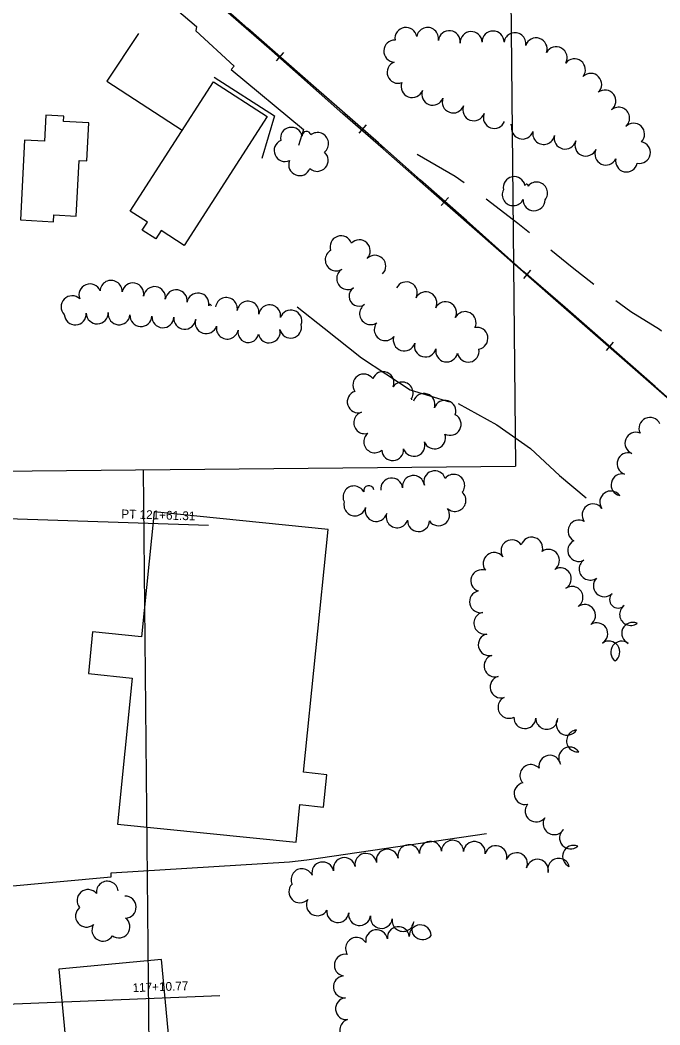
# Model space of a CAD drawing. Extents: x -25029 to 2274964, y -81170 to 687028.
# Drawn here: x -3935 to -3352, y -68032 to -67116 of the extents above; entities that cross this region are included whole.
import ezdxf

# ---------------------------------------------------------------- set-up
doc = ezdxf.new("R2010")
doc.units = 0
for name, color, linetype in [('BLDG', 7, 'Continuous'), ('Default', 7, 'Continuous'), ('DRIVWY', 7, 'Continuous'), ('RD_X_RR_1', 7, 'Continuous'), ('RR', 7, 'Continuous'), ('TREES', 7, 'Continuous'), ('WALL', 7, 'Continuous')]:
    doc.layers.add(name, color=color, linetype=linetype)

msp = doc.modelspace()

# ---------------------------------------------------------------- linework, layer by layer
at = {"layer": 'BLDG'}
for points in [[(-3710.3, -67204.07), (-3786, -67321.41), (-3806.95, -67307.9), (-3811.76, -67315.36), (-3824.04, -67307.44), (-3819.45, -67300.33), (-3835.17, -67290.19), (-3759.24, -67172.5)], [(-3905.01, -67299.85), (-3904.67, -67293.63), (-3884.3, -67294.72), (-3881.59, -67243.98), (-3874.52, -67244.36), (-3872.67, -67209.82), (-3895.96, -67208.57), (-3895.7, -67203.75), (-3911.85, -67202.88), (-3913.11, -67226.38), (-3931.26, -67225.41), (-3935.16, -67298.24)], [(-3683.93, -67865.26), (-3680.45, -67831.07), (-3658.95, -67833.25), (-3655.95, -67803.75), (-3677.34, -67801.58), (-3654.84, -67580.2), (-3813.11, -67564.12), (-3824.71, -67678.2), (-3869.31, -67673.67), (-3873.17, -67711.69), (-3833.21, -67715.75), (-3846.72, -67848.72)], [(-3856.97, -68100.09), (-3854.77, -68123.29), (-3834.57, -68121.38), (-3836.68, -68099.04), (-3794.95, -68095.09), (-3806.6, -67972.04), (-3899.99, -67980.88), (-3888.43, -68103.06)]]:
    msp.add_lwpolyline(points, close=True, dxfattribs=at)
at = {"layer": 'Default'}
for p, q in [((-3498.71, -66025.16), (-3484.02, -67522.6)), ((-4383.92, -67531.43), (-3484.02, -67522.6)), ((-3823.15, -67525.93), (-3813.45, -68514.64)), ((-4053.51, -67566.81), (-3763.85, -67576.44)), ((-4033.08, -68016.42), (-3753.55, -68005.06))]:
    msp.add_line(p, q, dxfattribs=at)
at = {"layer": 'DRIVWY'}
for points in [[(-3573.51, -67238.36), (-3538.86, -67258.18), (-3530.73, -67264.14)], [(-3510.65, -67279.04), (-3481.94, -67301.14), (-3471.22, -67309.78)], [(-3451.76, -67325.47), (-3432.45, -67341.11), (-3412.77, -67356.77)], [(-3392.72, -67371.68), (-3378.81, -67381.6), (-3352.85, -67397.87), (-3351.09, -67399.32)]]:
    msp.add_lwpolyline(points, dxfattribs=at)
at = {"layer": 'RD_X_RR_1'}
msp.add_lwpolyline([(-3338.49, -67466.69), (-3394.3, -67417.71), (-3449.6, -67369.51), (-3501.5, -67323.97), (-3560.76, -67272.02), (-3604.74, -67233.4), (-3641.21, -67201.63), (-3705.92, -67144.26), (-3766.77, -67090.93)], dxfattribs=at)
at = {"layer": 'RR'}
for p, q in [((-3695.37, -67145.65), (-3701.99, -67153.14)), ((-3620.24, -67211.6), (-3626.82, -67219.13)), ((-3545.16, -67277.69), (-3551.77, -67285.19)), ((-3470.34, -67343.95), (-3476.87, -67351.53)), ((-3394.94, -67409.73), (-3401.56, -67417.22))]:
    msp.add_line(p, q, dxfattribs=at)
msp.add_lwpolyline([(-3315.39, -67486.49), (-3356.83, -67450.14), (-3399.25, -67412.59), (-3438.66, -67377.86), (-3476.34, -67345.39), (-3528.75, -67298.8), (-3570.68, -67261.89), (-3608.97, -67228.08), (-3665.72, -67178.52), (-3727.78, -67123.68), (-3785.36, -67072.65)], dxfattribs=at)
at = {"layer": 'TREES'}
for centre, radius, start, end in [((-3583.86, -67132.75), 10, 9.29322, 189.29322), ((-3564.14, -67132.85), 10, 350.13406, 170.13406), ((-3544.37, -67135.79), 10, 352.95278, 172.95278), ((-3524.45, -67136.54), 10, 2.72567, 182.72567), ((-3504.46, -67136.06), 10, 0.00078, 180.00078), ((-3484.58, -67137.6), 10, 351.18296, 171.18296), ((-3594.11, -67144.36), 10, 87.82676, 267.82676), ((-3465.23, -67142.33), 10, 341.29702, 161.29702), ((-3447.01, -67150.39), 10, 330.9793, 150.9793), ((-3591.03, -67163.73), 10, 110.26741, 290.26741), ((-3430.35, -67161.35), 10, 322.38789, 142.38789), ((-3415.51, -67174.67), 10, 313.76908, 133.76908), ((-3578.2, -67176.64), 10, 159.35666, 339.35666), ((-3559.49, -67183.69), 10, 159.35666, 339.35666), ((-3402.54, -67189.85), 10, 307.24749, 127.24749), ((-3540.77, -67190.74), 10, 159.35666, 339.35666), ((-3522.06, -67197.79), 10, 159.35666, 339.35666), ((-3503.34, -67204.84), 10, 159.35666, 339.35666), ((-3390.06, -67205.48), 10, 309.94665, 129.94665), ((-3376.43, -67220.07), 10, 316.17336, 136.17336), ((-3688.16, -67223.88), 10, 11.38234, 191.38234), ((-3674.5, -67221.33), 3.9, 8.43662, 188.43662), ((-3664.42, -67228.59), 10, 308.46644, 128.46644), ((-3487.81, -67211.22), 0.644, 161.49384, 341.49384), ((-3477.68, -67214.51), 10, 162.03433, 342.03433), ((-3458.34, -67219.4), 10, 169.62353, 349.62353), ((-3693.97, -67235.02), 10, 113.56894, 293.56894), ((-3438.8, -67223.62), 10, 165.9901, 345.9901), ((-3419.91, -67230), 10, 156.69399, 336.69399), ((-3371.13, -67236.81), 10, 258.92439, 78.92439), ((-3664.77, -67243.95), 10, 228.88581, 48.88581), ((-3401.67, -67238.19), 10, 154.93813, 334.93813), ((-3680.66, -67247.83), 10, 158.58054, 338.58054), ((-3382.83, -67244.52), 10, 167.8786, 347.8786), ((-3485.18, -67268.71), 10, 11.33855, 191.33855), ((-3464.87, -67273.65), 10, 320.52268, 140.52268), ((-3486.07, -67275.2), 10, 153.15019, 333.15019), ((-3473.98, -67267.02), 1.42, 349.05215, 169.05215), ((-3467.15, -67279.86), 10, 179.16677, 359.16677), ((-3643.03, -67322.68), 10, 19.38781, 199.38781), ((-3626.42, -67326.33), 10, 315.8321, 135.8321), ((-3647.39, -67334.62), 10, 120.47028, 300.47028), ((-3612.19, -67340.38), 10, 314.91304, 134.91304), ((-3636.92, -67351.65), 10, 122.66671, 302.66671), ((-3871.79, -67366.57), 10, 21.43156, 201.43156), ((-3852.49, -67363.29), 10, 357.88244, 177.88244), ((-3832.69, -67365.61), 10, 348.75501, 168.75501), ((-3583.51, -67364.7), 10, 333.17101, 153.17101), ((-3812.99, -67369.01), 10, 351.67723, 171.67723), ((-3793.19, -67371.86), 10, 351.91104, 171.91104), ((-3773.41, -67374.81), 10, 351.10791, 171.10791), ((-3626.62, -67367.73), 9.1, 122.66671, 302.66671), ((-3565.67, -67373.73), 10, 333.17101, 153.17101), ((-3888.11, -67377.36), 10, 45.47328, 225.47328), ((-3762.34, -67376.55), 1.21, 351.00278, 171.00278), ((-3747.46, -67378.99), 10, 350.49467, 170.49467), ((-3727.74, -67382.3), 10, 350.49467, 170.49467), ((-3616.1, -67383.67), 10, 124.05608, 304.05608), ((-3547.82, -67382.76), 10, 333.17101, 153.17101), ((-3885.14, -67383.9), 10, 183.37279, 3.37279), ((-3865.17, -67383), 10, 181.78877, 1.78877), ((-3845.23, -67383.75), 10, 173.90466, 353.90466), ((-3708.01, -67385.6), 10, 350.49467, 170.49467), ((-3688.66, -67390.4), 10, 341.64973, 161.64973), ((-3529.97, -67391.78), 10, 333.17101, 153.17101), ((-3825.3, -67385.39), 10, 176.66211, 356.66211), ((-3805.33, -67386.42), 10, 177.41679, 357.41679), ((-3785.38, -67387.83), 10, 174.48697, 354.48697), ((-3765.91, -67391.84), 10, 162.2893, 342.2893), ((-3688.9, -67395.85), 10, 193.3196, 13.3196), ((-3602.72, -67398.23), 10, 141.15973, 321.15973), ((-3746.56, -67396.79), 10, 168.97134, 348.97134), ((-3727.47, -67400.51), 9.45, 168.97134, 348.97134), ((-3708.41, -67400.24), 10, 192.03052, 12.03052), ((-3519.18, -67406.12), 10, 280.76386, 100.76386), ((-3585.41, -67407.57), 10, 162.15216, 342.15216), ((-3566.2, -67413.11), 10, 165.67192, 345.67192), ((-3546.73, -67417.66), 10, 167.99323, 347.99323), ((-3527.13, -67417.84), 10, 190.94866, 10.94866), ((-3622.23, -67448.64), 10, 35.32689, 215.32689), ((-3604.78, -67446.55), 10, 338.35441, 158.35441), ((-3587.28, -67455.95), 10, 325.13226, 145.13226), ((-3627.33, -67463.94), 10, 107.85583, 287.85583), ((-3567.37, -67466.35), 10, 341.82744, 161.82744), ((-3578.82, -67461.85), 0.316, 324.75172, 144.75172), ((-3548.37, -67472.59), 10, 341.82744, 161.82744), ((-3621.4, -67483.04), 10, 106.59305, 286.59305), ((-3543.6, -67484.52), 10, 241.7542, 61.7542), ((-3361.51, -67488.19), 10, 25.22058, 205.22058), ((-3612.23, -67500.38), 10, 129.15451, 309.15451), ((-3557.7, -67496.82), 10, 200.43574, 20.43574), ((-3374.35, -67501.7), 10, 67.67211, 247.67211), ((-3576.52, -67503.6), 10, 199.2253, 19.2253), ((-3595.94, -67507.52), 10, 183.55071, 3.55071), ((-3381.47, -67520.38), 10, 70.64213, 250.64213), ((-3577.02, -67541.11), 10, 6.62517, 186.62517), ((-3557.59, -67536.85), 10, 18.11819, 198.11819), ((-3540.32, -67540.05), 10, 320.9002, 140.9002), ((-3386.94, -67539.58), 10, 77.54217, 257.54217), ((-3596.89, -67543.42), 10, 6.62517, 186.62517), ((-3631.19, -67550.66), 10, 27.68638, 207.68638), ((-3617.72, -67545.06), 4.71, 11.62643, 191.62643), ((-3539.22, -67553.81), 10, 228.24631, 48.24631), ((-3397.17, -67555.25), 10, 36.17429, 216.17429), ((-3630.37, -67557.84), 10, 165.31936, 345.31936), ((-3413.31, -67567.06), 10, 36.17361, 216.17361), ((-3611.05, -67563), 10, 164.73604, 344.73604), ((-3591.89, -67568.73), 10, 161.96141, 341.96141), ((-3554.14, -67566.91), 10, 214.33059, 34.33059), ((-3572.39, -67572.19), 10, 177.92541, 357.92541), ((-3426.17, -67581.74), 10, 61.37982, 241.37982), ((-3487.21, -67599.76), 10, 32.54208, 212.54208), ((-3469.23, -67597.32), 10, 342.87311, 162.87311), ((-3426.41, -67599.42), 10, 117.06701, 297.06701), ((-3503.5, -67611.32), 10, 38.20492, 218.20492), ((-3453.94, -67608.46), 10, 304.95263, 124.95263), ((-3416.01, -67616.43), 10, 125.81006, 305.81006), ((-3514.71, -67626.93), 10, 70.4143, 250.4143), ((-3443.16, -67625.29), 10, 300.31538, 120.31538), ((-3403.1, -67631.62), 10, 134.91264, 314.91264), ((-3515.88, -67646.11), 10, 102.60057, 282.60057), ((-3432.53, -67642.22), 10, 303.95029, 123.95029), ((-3390.57, -67644.2), 7.75, 134.91264, 314.91264), ((-3421.1, -67658.63), 10, 305.74484, 125.74484), ((-3379.16, -67657.73), 10, 126.40749, 306.40749), ((-3511.97, -67665.72), 10, 99.95521, 279.95521), ((-3410.03, -67675.27), 10, 301.57713, 121.57712), ((-3377.25, -67674.94), 10, 66.28197, 246.28197), ((-3507.92, -67685.29), 10, 103.45001, 283.45001), ((-3399.01, -67691.95), 10, 305.27514, 125.27514), ((-3387.26, -67692.1), 10, 53.24067, 233.24067), ((-3502.7, -67704.59), 10, 106.78803, 286.78803), ((-3497.15, -67723.8), 10, 105.47035, 285.47035), ((-3489.99, -67742.37), 10, 116.69643, 296.69643), ((-3475.5, -67751.79), 10, 177.25073, 357.25073), ((-3455.52, -67752.35), 10, 179.51351, 359.51351), ((-3437.03, -67757.73), 10, 148.04606, 328.04606), ((-3427.48, -67772.97), 10, 96.13152, 276.13152), ((-3452.74, -67796.05), 10, 10.59283, 190.59283), ((-3434.66, -67788.56), 10, 34.41679, 214.41679), ((-3470.01, -67804.57), 10, 41.91836, 221.91836), ((-3475.27, -67821.01), 10, 102.62187, 282.62187), ((-3465.18, -67836.89), 10, 142.21168, 322.21168), ((-3448.85, -67848.41), 10, 147.38459, 327.38459), ((-3433.88, -67861.36), 10, 130.92659, 310.92659), ((-3581.16, -67877.62), 10, 12.01677, 192.01677), ((-3561.43, -67874.47), 10, 6.13454, 186.13454), ((-3541.49, -67873.54), 10, 359.21409, 179.21409), ((-3521.55, -67874.73), 10, 353.97634, 173.97634), ((-3501.96, -67878.43), 10, 344.60084, 164.60084), ((-3431.17, -67878.15), 10, 67.42595, 247.42595), ((-3620.36, -67885.54), 10, 11.04692, 191.04692), ((-3600.74, -67881.67), 10, 11.30714, 191.30714), ((-3483.09, -67884.93), 10, 337.4031, 157.4031), ((-3659.6, -67893.33), 10, 11.76509, 191.76509), ((-3639.99, -67889.37), 10, 11.03445, 191.03445), ((-3464.06, -67890.78), 10, 348.43148, 168.43148), ((-3444.63, -67890.08), 10, 15.67693, 195.67693), ((-3678.53, -67899.42), 10, 23.93905, 203.93905), ((-3855.94, -67910.86), 10, 6.77234, 186.77234), ((-3680.51, -67910.47), 10, 135.68939, 315.68939), ((-3873.54, -67918.46), 10, 39.9433, 219.9433), ((-3839.69, -67924.44), 10, 271.38703, 91.38703), ((-3664.59, -67922.27), 10, 151.1903, 331.1903), ((-3874.89, -67932.64), 10, 129.13079, 309.13079), ((-3645.92, -67928.44), 10, 172.22583, 352.22583), ((-3626.11, -67931.15), 10, 172.22583, 352.22583), ((-3606.29, -67933.85), 10, 172.22583, 352.22583), ((-3859.96, -67945.46), 10, 149.59638, 329.59638), ((-3845.39, -67942.48), 10, 233.53114, 53.53114), ((-3590.73, -67952.24), 10, 6.41888, 186.41888), ((-3586.47, -67936.56), 10, 172.22215, 352.22215), ((-3570.81, -67950.68), 10, 2.53292, 182.53292), ((-3568.69, -67944.08), 10, 141.95829, 321.95829), ((-3628.83, -67962.12), 10, 32.34198, 212.34198), ((-3610.52, -67955.07), 10, 9.8372, 189.8372), ((-3639.09, -67977.31), 10, 79.52851, 259.52851), ((-3639.94, -67997.09), 10, 95.57058, 275.57058), ((-3638, -68017), 10, 95.57256, 275.57256), ((-3634.08, -68036.51), 10, 107.10289, 287.10289)]:
    msp.add_arc(centre, radius, start, end, dxfattribs=at)
at = {"layer": 'WALL'}
for points in [[(-3962.19, -66962.56), (-3920.45, -66996.74), (-3866.77, -67042.13), (-3815.06, -67087.45), (-3774.66, -67121.83), (-3775.24, -67125.76), (-3740.3, -67158.08), (-3743.06, -67161.22), (-3677.21, -67215.81), (-3681.77, -67230.31)], [(-3827.4, -67128.38), (-3856.32, -67171.89), (-3787.62, -67216.49)], [(-3758.46, -67168.24), (-3703.47, -67203.46), (-3715.03, -67242.08)], [(-3682.92, -67377.35), (-3658.24, -67396.71), (-3624.26, -67423.97), (-3579.98, -67453.11), (-3544.23, -67463.88)], [(-3536.24, -67465.4), (-3501.17, -67484.8), (-3470.39, -67506.57), (-3443.98, -67531.2), (-3419.73, -67551.32)], [(-4002.18, -67910.41), (-3852.47, -67896.83), (-3852.45, -67893.25), (-3689.84, -67883.24), (-3674.11, -67881.22), (-3510.52, -67857.25)]]:
    msp.add_lwpolyline(points, dxfattribs=at)

# ---------------------------------------------------------------- texts
at = {"layer": 'Default'}
for s, height, rotation, p in [('PT 121+61.31', 7.9999, 358.26393, (-3843.3, -67570.02)), ('117+10.77', 8, 2.18862, (-3832.78, -68001.96))]:
    msp.add_text(s, height=height, rotation=rotation, dxfattribs=at).set_placement(p)

doc.saveas('drawing.dxf')
